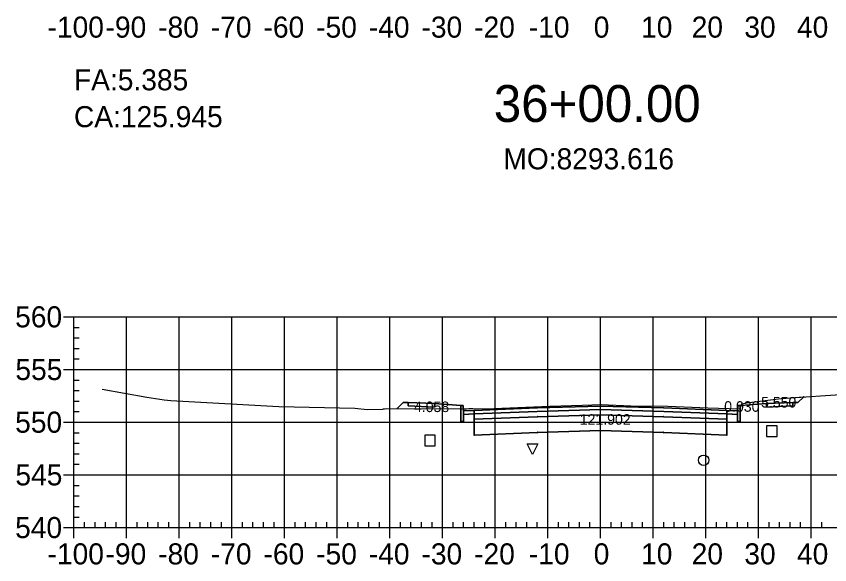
# Model space of a CAD drawing. Extents: x 704834 to 709892, y 372981 to 377533.
# Drawn here: x 707125.9 to 707280.4, y 373635.8 to 373739.9 of the extents above; entities that cross this region are included whole.
import ezdxf

# ---------------------------------------------------------------- set-up
doc = ezdxf.new("R2010")
doc.units = 0
for name, color, linetype in [('1', 7, 'Continuous'), ('10', 7, 'Continuous'), ('13', 7, 'Continuous'), ('14', 7, 'Continuous'), ('4', 7, 'Continuous'), ('57', 7, 'Continuous'), ('59', 7, 'Continuous'), ('Default_Xsect', 7, 'Continuous'), ('Existing', 7, 'Continuous')]:
    doc.layers.add(name, color=color, linetype=linetype)

msp = doc.modelspace()

# ---------------------------------------------------------------- linework, layer by layer
for points in [[(707199.37, 373666.53), (707198.23, 373665.39)], [(707200.37, 373666.57), (707199.37, 373666.53)], [(707210.37, 373665.97), (707205.37, 373666.37)], [(707263.37, 373665.97), (707268.37, 373666.37)], [(707273.37, 373666.57), (707274.37, 373666.53)], [(707274.37, 373666.53), (707275.47, 373667.62)]]:
    msp.add_lwpolyline(points)
for points in [[(707205.37, 373666.37), (707200.37, 373666.57), (707200.37, 373665.9), (707205.37, 373665.7)], [(707268.37, 373665.7), (707273.37, 373665.9), (707273.37, 373666.57), (707268.37, 373666.37)], [(707210.87, 373664.97), (707210.79, 373665.97), (707210.37, 373665.97), (707210.37, 373662.97), (707210.87, 373662.97)], [(707212.87, 373665.05), (707210.87, 373664.97), (707210.87, 373664.3), (707212.87, 373664.38)], [(707236.87, 373665.22), (707248.87, 373664.86), (707260.87, 373664.38), (707260.87, 373665.05), (707248.87, 373665.53), (707236.87, 373665.89), (707224.87, 373665.53), (707212.87, 373665.05), (707212.87, 373664.38), (707224.87, 373664.86)], [(707236.87, 373664.22), (707248.87, 373663.86), (707260.87, 373663.38), (707260.87, 373664.38), (707248.87, 373664.86), (707236.87, 373665.22), (707224.87, 373664.86), (707212.87, 373664.38), (707212.87, 373663.38), (707224.87, 373663.86)], [(707236.82, 373665.17), (707236.92, 373665.17), (707236.92, 373665.27), (707236.82, 373665.27)], [(707260.87, 373664.38), (707262.87, 373664.3), (707262.87, 373664.97), (707260.87, 373665.05)], [(707262.87, 373662.97), (707263.37, 373662.97), (707263.37, 373665.97), (707262.96, 373665.97), (707262.87, 373664.97)], [(707212.82, 373663.33), (707212.92, 373663.33), (707212.92, 373663.43), (707212.82, 373663.43)], [(707236.87, 373661.22), (707248.87, 373660.86), (707260.87, 373660.38), (707260.87, 373663.38), (707248.87, 373663.86), (707236.87, 373664.22), (707224.87, 373663.86), (707212.87, 373663.38), (707212.87, 373660.38), (707224.87, 373660.86)], [(707224.82, 373663.81), (707224.92, 373663.81), (707224.92, 373663.91), (707224.82, 373663.91)], [(707236.82, 373664.17), (707236.92, 373664.17), (707236.92, 373664.27), (707236.82, 373664.27)], [(707248.82, 373663.81), (707248.92, 373663.81), (707248.92, 373663.91), (707248.82, 373663.91)], [(707260.82, 373663.33), (707260.92, 373663.33), (707260.92, 373663.43), (707260.82, 373663.43)], [(707212.82, 373660.33), (707212.92, 373660.33), (707212.92, 373660.43), (707212.82, 373660.43)], [(707224.82, 373660.81), (707224.92, 373660.81), (707224.92, 373660.91), (707224.82, 373660.91)], [(707236.82, 373661.17), (707236.92, 373661.17), (707236.92, 373661.27), (707236.82, 373661.27)], [(707248.82, 373660.81), (707248.92, 373660.81), (707248.92, 373660.91), (707248.82, 373660.91)], [(707260.82, 373660.33), (707260.92, 373660.33), (707260.92, 373660.43), (707260.82, 373660.43)]]:
    msp.add_lwpolyline(points, close=True)
at = {"layer": '1'}
for points in [[(707198.23, 373665.39), (707210.37, 373665.33), (707210.37, 373665.97), (707205.37, 373666.37), (707205.37, 373665.7), (707200.37, 373665.9), (707200.37, 373666.57), (707199.37, 373666.53)], [(707263.61, 373665.98), (707263.76, 373666.33), (707264.59, 373666.47), (707264.62, 373666.48), (707271.16, 373667.33), (707275.47, 373667.62), (707274.37, 373666.53), (707273.37, 373666.57), (707273.37, 373665.9), (707268.37, 373665.7), (707268.37, 373666.37)], [(707210.37, 373665.33), (707211.07, 373665.33), (707211.45, 373665.38), (707211.89, 373665.41), (707212.3, 373665.43), (707212.59, 373665.42), (707213.05, 373665.33), (707216.62, 373665.41), (707227.27, 373665.84), (707233.42, 373666.05), (707236.99, 373666.16), (707242.61, 373665.92), (707249.66, 373665.86), (707257.23, 373665.56), (707263.32, 373665.33), (707263.37, 373665.46), (707263.37, 373662.97), (707262.87, 373662.97), (707262.87, 373664.3), (707260.87, 373664.38), (707260.87, 373663.38), (707260.87, 373660.38), (707248.87, 373660.86), (707236.87, 373661.22), (707224.87, 373660.86), (707212.87, 373660.38), (707212.87, 373663.38), (707212.87, 373664.38), (707210.87, 373664.3), (707210.87, 373662.97), (707210.37, 373662.97)], [(707263.37, 373665.46), (707263.43, 373665.59), (707263.61, 373665.98), (707263.37, 373665.97)], [(707223.97, 373656.71), (707222.97, 373658.71), (707224.97, 373658.71)]]:
    msp.add_lwpolyline(points, close=True, dxfattribs=at)
at = {"layer": '10'}
msp.add_lwpolyline([(707203.49, 373658.36), (707205.49, 373658.36), (707205.49, 373660.36), (707203.49, 373660.36)], close=True, dxfattribs=at)
at = {"layer": '13'}
msp.add_circle((707256.46, 373655.59), 1, dxfattribs=at)
at = {"layer": '14'}
for points in [[(707275.47, 373667.62), (707275.47, 373667.67), (707275.47, 373667.62), (707275.42, 373667.62), (707275.47, 373667.62), (707275.47, 373667.57), (707275.47, 373667.62), (707275.52, 373667.62)], [(707198.23, 373665.39), (707198.23, 373665.44), (707198.23, 373665.39), (707198.18, 373665.39), (707198.23, 373665.39), (707198.23, 373665.34), (707198.23, 373665.39), (707198.28, 373665.39)], [(707212.87, 373665.05), (707212.87, 373665.1), (707212.87, 373665.05), (707212.82, 373665.05), (707212.87, 373665.05), (707212.87, 373665), (707212.87, 373665.05), (707212.92, 373665.05)], [(707224.87, 373665.53), (707224.87, 373665.58), (707224.87, 373665.53), (707224.82, 373665.53), (707224.87, 373665.53), (707224.87, 373665.48), (707224.87, 373665.53), (707224.92, 373665.53)], [(707236.87, 373665.89), (707236.87, 373665.94), (707236.87, 373665.89), (707236.82, 373665.89), (707236.87, 373665.89), (707236.87, 373665.84), (707236.87, 373665.89), (707236.92, 373665.89)], [(707248.87, 373665.53), (707248.87, 373665.58), (707248.87, 373665.53), (707248.82, 373665.53), (707248.87, 373665.53), (707248.87, 373665.48), (707248.87, 373665.53), (707248.92, 373665.53)], [(707260.87, 373665.05), (707260.87, 373665.1), (707260.87, 373665.05), (707260.82, 373665.05), (707260.87, 373665.05), (707260.87, 373665), (707260.87, 373665.05), (707260.92, 373665.05)]]:
    msp.add_lwpolyline(points, dxfattribs=at)
at = {"layer": '4'}
msp.add_lwpolyline([(707268.39, 373660.1), (707270.39, 373660.1), (707270.39, 373662.1), (707268.39, 373662.1)], close=True, dxfattribs=at)
at = {"layer": '57'}
for p, q in [((707134.87, 373682.82), (707136.87, 373682.82)), ((707136.87, 373682.82), (707336.87, 373682.82)), ((707136.87, 373642.82), (707136.87, 373682.82)), ((707136.87, 373642.82), (707136.87, 373682.82)), ((707146.87, 373642.82), (707146.87, 373682.82)), ((707156.87, 373642.82), (707156.87, 373682.82)), ((707166.87, 373642.82), (707166.87, 373682.82)), ((707176.87, 373642.82), (707176.87, 373682.82)), ((707186.87, 373642.82), (707186.87, 373682.82)), ((707196.87, 373642.82), (707196.87, 373682.82)), ((707206.87, 373642.82), (707206.87, 373682.82)), ((707216.87, 373642.82), (707216.87, 373682.82)), ((707226.87, 373642.82), (707226.87, 373682.82)), ((707236.87, 373642.82), (707236.87, 373682.82)), ((707246.87, 373642.82), (707246.87, 373682.82)), ((707256.87, 373642.82), (707256.87, 373682.82)), ((707266.87, 373642.82), (707266.87, 373682.82)), ((707276.87, 373642.82), (707276.87, 373682.82)), ((707136.87, 373680.82), (707137.87, 373680.82)), ((707136.87, 373678.82), (707137.87, 373678.82)), ((707136.87, 373676.82), (707137.87, 373676.82)), ((707136.87, 373674.82), (707137.87, 373674.82)), ((707134.87, 373672.82), (707136.87, 373672.82)), ((707136.87, 373672.82), (707336.87, 373672.82)), ((707136.87, 373670.82), (707137.87, 373670.82)), ((707136.87, 373668.82), (707137.87, 373668.82)), ((707136.87, 373666.82), (707137.87, 373666.82)), ((707136.87, 373664.82), (707137.87, 373664.82)), ((707134.87, 373662.82), (707136.87, 373662.82)), ((707136.87, 373662.82), (707336.87, 373662.82)), ((707136.87, 373660.82), (707137.87, 373660.82)), ((707136.87, 373658.82), (707137.87, 373658.82)), ((707136.87, 373656.82), (707137.87, 373656.82)), ((707136.87, 373654.82), (707137.87, 373654.82)), ((707134.87, 373652.82), (707136.87, 373652.82)), ((707136.87, 373652.82), (707336.87, 373652.82)), ((707136.87, 373650.82), (707137.87, 373650.82)), ((707136.87, 373648.82), (707137.87, 373648.82)), ((707136.87, 373646.82), (707137.87, 373646.82)), ((707136.87, 373644.82), (707137.87, 373644.82)), ((707138.87, 373642.82), (707138.87, 373643.82)), ((707140.87, 373642.82), (707140.87, 373643.82)), ((707142.87, 373642.82), (707142.87, 373643.82)), ((707144.87, 373642.82), (707144.87, 373643.82)), ((707148.87, 373642.82), (707148.87, 373643.82)), ((707150.87, 373642.82), (707150.87, 373643.82)), ((707152.87, 373642.82), (707152.87, 373643.82)), ((707154.87, 373642.82), (707154.87, 373643.82)), ((707158.87, 373642.82), (707158.87, 373643.82)), ((707160.87, 373642.82), (707160.87, 373643.82)), ((707162.87, 373642.82), (707162.87, 373643.82)), ((707164.87, 373642.82), (707164.87, 373643.82)), ((707168.87, 373642.82), (707168.87, 373643.82)), ((707170.87, 373642.82), (707170.87, 373643.82)), ((707172.87, 373642.82), (707172.87, 373643.82)), ((707174.87, 373642.82), (707174.87, 373643.82)), ((707178.87, 373642.82), (707178.87, 373643.82)), ((707180.87, 373642.82), (707180.87, 373643.82)), ((707182.87, 373642.82), (707182.87, 373643.82)), ((707184.87, 373642.82), (707184.87, 373643.82)), ((707188.87, 373642.82), (707188.87, 373643.82)), ((707190.87, 373642.82), (707190.87, 373643.82)), ((707192.87, 373642.82), (707192.87, 373643.82)), ((707194.87, 373642.82), (707194.87, 373643.82)), ((707198.87, 373642.82), (707198.87, 373643.82)), ((707200.87, 373642.82), (707200.87, 373643.82)), ((707202.87, 373642.82), (707202.87, 373643.82)), ((707204.87, 373642.82), (707204.87, 373643.82)), ((707208.87, 373642.82), (707208.87, 373643.82)), ((707210.87, 373642.82), (707210.87, 373643.82)), ((707212.87, 373642.82), (707212.87, 373643.82)), ((707214.87, 373642.82), (707214.87, 373643.82)), ((707218.87, 373642.82), (707218.87, 373643.82)), ((707220.87, 373642.82), (707220.87, 373643.82)), ((707222.87, 373642.82), (707222.87, 373643.82)), ((707224.87, 373642.82), (707224.87, 373643.82)), ((707228.87, 373642.82), (707228.87, 373643.82)), ((707230.87, 373642.82), (707230.87, 373643.82)), ((707232.87, 373642.82), (707232.87, 373643.82)), ((707234.87, 373642.82), (707234.87, 373643.82)), ((707238.87, 373642.82), (707238.87, 373643.82)), ((707240.87, 373642.82), (707240.87, 373643.82)), ((707242.87, 373642.82), (707242.87, 373643.82)), ((707244.87, 373642.82), (707244.87, 373643.82)), ((707248.87, 373642.82), (707248.87, 373643.82)), ((707250.87, 373642.82), (707250.87, 373643.82)), ((707252.87, 373642.82), (707252.87, 373643.82)), ((707254.87, 373642.82), (707254.87, 373643.82)), ((707258.87, 373642.82), (707258.87, 373643.82)), ((707260.87, 373642.82), (707260.87, 373643.82)), ((707262.87, 373642.82), (707262.87, 373643.82)), ((707264.87, 373642.82), (707264.87, 373643.82)), ((707268.87, 373642.82), (707268.87, 373643.82)), ((707270.87, 373642.82), (707270.87, 373643.82)), ((707272.87, 373642.82), (707272.87, 373643.82)), ((707274.87, 373642.82), (707274.87, 373643.82)), ((707278.87, 373642.82), (707278.87, 373643.82)), ((707134.87, 373642.82), (707136.87, 373642.82)), ((707136.87, 373642.82), (707336.87, 373642.82)), ((707136.87, 373642.82), (707336.87, 373642.82)), ((707136.87, 373640.82), (707136.87, 373642.82)), ((707146.87, 373640.82), (707146.87, 373642.82)), ((707156.87, 373640.82), (707156.87, 373642.82)), ((707166.87, 373640.82), (707166.87, 373642.82)), ((707176.87, 373640.82), (707176.87, 373642.82)), ((707186.87, 373640.82), (707186.87, 373642.82)), ((707196.87, 373640.82), (707196.87, 373642.82)), ((707206.87, 373640.82), (707206.87, 373642.82)), ((707216.87, 373640.82), (707216.87, 373642.82)), ((707226.87, 373640.82), (707226.87, 373642.82)), ((707236.87, 373640.82), (707236.87, 373642.82)), ((707246.87, 373640.82), (707246.87, 373642.82)), ((707256.87, 373640.82), (707256.87, 373642.82)), ((707266.87, 373640.82), (707266.87, 373642.82)), ((707276.87, 373640.82), (707276.87, 373642.82))]:
    msp.add_line(p, q, dxfattribs=at)
at = {"layer": 'Default_Xsect'}
msp.add_lwpolyline([(707198.23, 373665.39), (707199.37, 373666.53), (707200.37, 373666.57), (707205.37, 373666.37), (707210.37, 373665.97), (707210.79, 373665.97), (707210.87, 373664.97), (707212.87, 373665.05), (707224.87, 373665.53), (707236.87, 373665.89), (707248.87, 373665.53), (707260.87, 373665.05), (707262.87, 373664.97), (707262.96, 373665.97), (707263.37, 373665.97), (707268.37, 373666.37), (707273.37, 373666.57), (707274.37, 373666.53), (707275.47, 373667.62)], dxfattribs=at)
at = {"layer": 'Existing'}
msp.add_lwpolyline([(707142.2, 373669.12), (707150.73, 373667.56), (707154.01, 373667.05), (707155.24, 373666.96), (707170.07, 373666.11), (707175.77, 373665.81), (707190.19, 373665.46), (707192.56, 373665.21), (707195.52, 373665.31), (707195.66, 373665.33), (707195.82, 373665.35), (707196.15, 373665.4), (707211.07, 373665.33), (707211.45, 373665.38), (707211.89, 373665.41), (707212.3, 373665.43), (707212.59, 373665.42), (707213.05, 373665.33), (707216.62, 373665.41), (707227.27, 373665.84), (707233.42, 373666.05), (707236.99, 373666.16), (707242.61, 373665.92), (707249.66, 373665.86), (707257.23, 373665.56), (707263.32, 373665.33), (707263.43, 373665.59), (707263.76, 373666.33), (707264.59, 373666.47), (707264.62, 373666.48), (707271.16, 373667.33), (707284.3, 373668.22)], dxfattribs=at)

# ---------------------------------------------------------------- texts
msp.add_text('CA:125.945', height=4).set_placement((707136.87, 373718.82))
at = {"layer": '1'}
msp.add_text('36+00.00', height=7, dxfattribs=at).set_placement((707216.6, 373719.82))
at = {"layer": '14'}
for p in [(707200.34, 373666.52), (707273.34, 373666.52), (707200.34, 373665.85), (707205.34, 373665.65), (707268.34, 373665.65), (707273.34, 373665.85)]:
    msp.add_text('+', height=0.1, dxfattribs=at).set_placement(p)
at = {"layer": '57'}
for s, p in [('-100', (707131.86, 373735.82)), ('-90', (707142.87, 373735.82)), ('-80', (707152.87, 373735.82)), ('-70', (707162.87, 373735.82)), ('-60', (707172.87, 373735.82)), ('-50', (707182.87, 373735.82)), ('-40', (707192.87, 373735.82)), ('-30', (707202.87, 373735.82)), ('-20', (707212.87, 373735.82)), ('-10', (707223.26, 373735.82)), ('0', (707235.58, 373735.82)), ('10', (707244.57, 373735.82)), ('20', (707254.18, 373735.82)), ('30', (707264.18, 373735.82)), ('40', (707274.18, 373735.82)), ('560', (707125.7, 373680.82)), ('555', (707125.75, 373670.82)), ('550', (707125.7, 373660.82)), ('545', (707125.75, 373650.82)), ('540', (707125.7, 373640.82)), ('-100', (707131.86, 373635.82)), ('-90', (707142.87, 373635.82)), ('-80', (707152.87, 373635.82)), ('-70', (707162.87, 373635.82)), ('-60', (707172.87, 373635.82)), ('-50', (707182.87, 373635.82)), ('-40', (707192.87, 373635.82)), ('-30', (707202.87, 373635.82)), ('-20', (707212.87, 373635.82)), ('-10', (707223.26, 373635.82)), ('0', (707235.58, 373635.82)), ('10', (707244.57, 373635.82)), ('20', (707254.18, 373635.82)), ('30', (707264.18, 373635.82)), ('40', (707274.18, 373635.82))]:
    msp.add_text(s, height=4, dxfattribs=at).set_placement(p)
at = {"layer": '59'}
for s, height, p in [('FA:5.385', 4, (707136.87, 373725.82)), ('MO:8293.616', 4, (707218.42, 373710.82)), ('4.058', 2, (707201.44, 373664.74)), ('0.030', 2, (707260.36, 373664.8)), ('5.550', 2, (707267.36, 373665.6)), ('121.902', 2, (707232.92, 373662.34))]:
    msp.add_text(s, height=height, dxfattribs=at).set_placement(p)

doc.saveas('drawing.dxf')
